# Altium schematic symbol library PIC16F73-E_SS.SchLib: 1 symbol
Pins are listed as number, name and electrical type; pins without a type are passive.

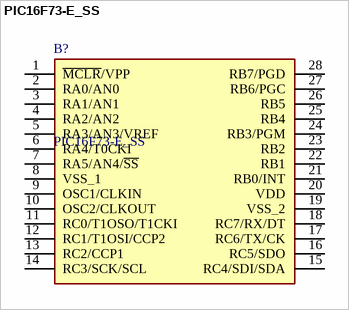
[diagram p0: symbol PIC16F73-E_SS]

## PIC16F73-E_SS
designator B?
Microchip PIC16F73-E/SS, 8bit PIC Microcontroller, 20MHz, 4096 B Flash, 28-Pin SSOP; Geometry.Height: 1.98mm
footprint SOP65P784X198-28N
pins: 1 ~{MCLR}/VPP, 2 RA0/AN0, 3 RA1/AN1, 4 RA2/AN2, 5 RA3/AN3/VREF, 6 RA4/T0CKI, 7 RA5/AN4/~{SS}, 8 VSS_1, 9 OSC1/CLKIN, 10 OSC2/CLKOUT, 11 RC0/T1OSO/T1CKI, 12 RC1/T1OSI/CCP2, 13 RC2/CCP1, 14 RC3/SCK/SCL, 15 RC4/SDI/SDA, 16 RC5/SDO, 17 RC6/TX/CK, 18 RC7/RX/DT, 19 VSS_2, 20 VDD, 21 RB0/INT, 22 RB1, 23 RB2, 24 RB3/PGM, 25 RB4, 26 RB5, 27 RB6/PGC, 28 RB7/PGD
